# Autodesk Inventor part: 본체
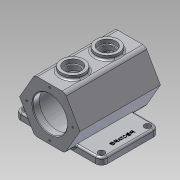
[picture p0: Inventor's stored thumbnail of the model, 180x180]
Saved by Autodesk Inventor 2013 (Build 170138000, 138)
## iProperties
Created: 2021-06
Part Number: 본체
Material: 알루미늄 6061
Document SubType Name: Modeling
Designer: max6
Density: 2.71 g/cm^3
Mass: 1500.47 g
Surface Area: 1112.81 cm^2
Volume: 553.677 cm^3
Author: max6
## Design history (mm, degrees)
sketch "스케치1" dims "d2" = 105
  geometry: L1 (26.25, -45.466)-(-26.25, -45.466); L2 (-26.25, -45.466)-(-52.5, 0); L3 (-52.5, 0)-(-26.25, 45.466); L4 (-26.25, 45.466)-(26.25, 45.466); L5 (26.25, 45.466)-(52.5, 0); L6 (52.5, 0)-(26.25, -45.466); 3 further points
  constraints: 12 end point, 2 coincident, 1 horizontal, 16 other
extrude "돌출1" new body sketch "스케치1" stored distance "d4" = 140; taper "d5" = 0 deg
node "작업 평면1"
sketch "스케치2"
  geometry: L1 (0, -98)-(0, 98) reference; L2 (-73.5, 0)-(73.5, 0) reference; L3 (-75, -55)-(75, -55); L4 (75, -55)-(75, 45); L5 (75, 45)-(-75, 45); L6 (-75, 45)-(-75, -55); L7 (-75, -55)-(75, 45); L8 (75, -55)-(-75, 45); L9 (-26.25, -70)-(-52.5, -70) reference; L10 (26.25, 70)-(52.5, 70) reference; 1 further point
  constraints: 12 end point, 2 midpoint, 2 parallel, 1 horizontal, 1 perpendicular, 1 point on line
  dimensions: "d12" = 150 distance of L4.end L5.end; "d13" = 15 distance between parallel lines of L9 L3; "d14" = 25 distance between parallel lines of L10 L5
extrude "돌출2" join sketch "스케치2" distance "d15" = 12; taper "d16" = 0 deg
sketch "스케치5"
  geometry: C1 r 30 at (0, 0); 1 further point
  constraints: 1 centre point, 1 coincident
  dimensions: "d33" = 60 diameter of C1
extrude "돌출3" cut sketch "스케치5" distance "d35" = 12; taper "d36" = 0 deg
sketch "스케치6"
  geometry: C1 r 30 at (0, 0); 1 further point
  constraints: 1 centre point, 1 coincident
  dimensions: "d37" = 60 diameter of C1
extrude "돌출4" cut sketch "스케치6" distance "d39" = 12; taper "d40" = 0 deg
sketch "스케치7"
  geometry: C1 r 30 at (0, 0) reference; C2 r 37.5 at (0, 0)
  constraints: 1 centre point, 1 coincident
  dimensions: "d41" = 75 diameter of C2
extrude "돌출5" cut sketch "스케치7" distance "d43" = 116; taper "d44" = 0 deg
node "작업 평면2"
sketch "스케치8"
  geometry: L1 (0, -98)-(0, 98) reference; L2 (-105, 0)-(105, 0) reference; L3 (26.25, -70)-(-26.25, -70) reference; L4 (-26.25, 70)-(26.25, 70) reference; C1 r 20 at (0, -30); C2 r 20 at (0, 30); 1 further point
  constraints: 2 centre point, 2 point on line
  dimensions: "d46" = 40 diameter of C1; "d48" = 40 diameter of C2; "d50" = 60 distance of C2.centre C1.centre; "d131" = 40 distance from line of L4 C2.centre
extrude "돌출6" join sketch "스케치8" stored distance "d51" = 116; taper "d52" = 0 deg
sketch "스케치9"
  geometry: C1 r 20 at (0, 0) reference; C2 r 15 at (0, 0); C3 r 20 at (0, 60) reference; C4 r 15 at (0, 60); 1 further point
  constraints: 2 centre point, 2 coincident
  dimensions: "d53" = 30 diameter of C2; "d55" = 30 diameter of C4
extrude "돌출7" cut sketch "스케치9" distance "d56" = 8; taper "d57" = 0 deg
sketch "스케치10"
  geometry: C1 r 15 at (0, 0) reference; C2 r 15 at (0, 60) reference; C3 r 12.5 at (0, 0); C4 r 12.5 at (0, 60); 1 further point
  constraints: 2 centre point, 2 coincident
  dimensions: "d58" = 25 diameter of C3; "d60" = 25 diameter of C4
extrude "돌출8" cut sketch "스케치10" stored distance "d61" = 8; taper "d62" = 0 deg
fillet "모깎기1" dims "d90" = 10
sketch "스케치14"
  geometry: L1 (65, 45)-(-65, 45) reference; L2 (75, -45)-(75, 35) reference; L3 (-65, -55)-(65, -55) reference; L4 (-75, 35)-(-75, -45) reference; C1 r 5.5 at (-65, -45); C2 r 5.5 at (-65, 35); C3 r 5.5 at (65, 35); C4 r 5.5 at (65, -45); A1 r 10 centre (-65, 35) between (-65, 45) and (-75, 35) reference; A2 r 10 centre (65, 35) between (75, 35) and (65, 45) reference; A3 r 10 centre (65, -45) between (65, -55) and (75, -45) reference; A4 r 10 centre (-65, -45) between (-75, -45) and (-65, -55) reference; 1 further point
  constraints: 4 centre point, 4 coincident
  dimensions: "d91" = 11 diameter of C1; "d93" = 11 diameter of C2; "d94" = 11 diameter of C4; "d95" = 11 diameter of C3
extrude "돌출9" cut sketch "스케치14" stored distance "d96" = 8; taper "d97" = 0 deg
fillet "모깎기2" dims "d98" = 8
fillet "모깎기3" dims "d99" = 5
fillet "모깎기4" dims "d100" = 3
chamfer "모따기1" distance "d101" = 1; stored, may be unused: second distance "d102" = 2, angle "d103" = 45 deg
sketch "스케치15" dims "d104" = 80
  geometry: L1 (-105, 0)-(105, 0) reference; L2 (0, 70.5)-(0, -73) reference; L3 (0, 0)-(28.284, -28.284); C1 r 31 at (0, 0) reference; 1 further point
  constraints: 2 coincident, 2 end point, 3 other
  dimensions: "d106" = 45 deg angle of L2 L3
hole "구멍3" sketch "스케치15" at (28.284, -28.284) diameter "d108" = 3.242; stored, may be unused: countersink angle "d112" = 90 deg, drill point angle "d114" = 118 deg; dims "d109" = 8, "d110" = 4, "d111" = 2, "d113" = 10
sketch "스케치16"
  geometry: L1 (-105, 0)-(105, 0) reference; L2 (0, -70.5)-(0, 73) reference; C1 r 31 at (0, 0) reference; A1 r 40 centre (0, 0) between (0, 40) and (40, 0); 2 further points
  constraints: 4 point on circle, 4 point on line, 1 centre point, 1 coincident
  dimensions: "d118" = 80 diameter of A1
hole "구멍4" sketch "스케치16" at (0, 40), (40, 0), (0, -40), (-40, 0) diameter "d120" = 3.242; stored, may be unused: countersink angle "d124" = 90 deg, drill point angle "d126" = 118 deg; dims "d121" = 8, "d122" = 4, "d123" = 2, "d125" = 10
sketch "스케치17"
  geometry: L1 (75, -45)-(75, 35) reference; L2 (65, 45)-(32.293, 45) reference; 2 further points
  constraints: 1 other
  dimensions: "d127" = 14 distance from line of L1 point (61, -5); "d128" = 50 distance from line of L2 point (61, -5)
feature "엠보싱2" sketch "스케치17" dims "d2" = 105, "d15" = 12, "d129" = 0.5, "d130" = 0
node "솔리드1"
pattern_circular "원형 패턴2" dims angle "d116" = 360 deg
node "투영된 루프1"
node "투영된 루프2"
node "투영된 루프3"
other parameters: "d45" = 52.5
